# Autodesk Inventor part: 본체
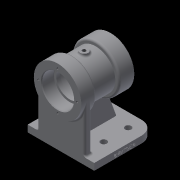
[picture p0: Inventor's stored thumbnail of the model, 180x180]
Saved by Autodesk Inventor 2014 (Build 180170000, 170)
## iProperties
Created: 2020-06
Part Number: 본체
Material: Generic
Document SubType Name: Modeling
Designer: kh
Density: 1 g/cm^3
Appearance: Default
Author: kh
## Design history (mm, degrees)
sketch "Sketch1"
  geometry: L1 (-45, -49)-(45, -49); L2 (45, -49)-(45, 49); L3 (45, 49)-(-45, 49); L4 (-45, 49)-(-45, -49); L5 (-45, -49)-(45, 49); L6 (45, -49)-(-45, 49); 1 further point
  constraints: 12 end point, 2 midpoint, 2 parallel, 1 horizontal, 1 perpendicular
  dimensions: "d0" = 90 distance of L2.end L3.end; "d1" = 98 distance of L1.end L2.end
extrude "Extrusion1" new body sketch "Sketch1" distance "d2" = 10; taper "d3" = 0 deg
fillet "Fillet1" dims "d4" = 20
workplane "Work Plane1"
sketch "Sketch2"
  geometry: L1 (-15.944, 80)-(113.944, 80); L2 (0, 0)-(98, 0) reference; C1 r 35 at (49, 80); 3 further points
  constraints: 2 end point, 2 midpoint, 1 centre point, 1 coincident, 1 horizontal, 1 vertical alignment
  dimensions: "d6" = 80 distance between parallel lines of L2 L1; "d7" = 70 diameter of C1
extrude "Extrusion2" join sketch "Sketch2" distance "d8" = 22; taper "d9" = 0 deg
sketch "Sketch3"
  geometry: C1 r 35 at (0, 0) reference; C2 r 29 at (0, 0); 1 further point
  constraints: 1 centre point, 1 coincident
  dimensions: "d10" = 58 diameter of C2
extrude "Extrusion3" join sketch "Sketch3" distance "d11" = 34; taper "d12" = 0 deg
sketch "Sketch4"
  geometry: C1 r 29 at (0, 0) reference; C2 r 35 at (0, 0); 1 further point
  constraints: 1 centre point, 1 coincident
  dimensions: "d13" = 70 diameter of C2
extrude "Extrusion4" join sketch "Sketch4" distance "d14" = 22; taper "d15" = 0 deg
workplane "Work Plane3"
sketch "Sketch5"
  geometry: L1 (50, 35)-(50, -35) reference; L2 (11, 35)-(11, -35); C1 r 6 at (11, 0); 2 further points
  constraints: 2 end point, 1 centre point, 1 coincident, 1 horizontal alignment, 1 midpoint, 1 parallel
  dimensions: "d18" = 39 distance between parallel lines of L2 L1; "d19" = 12 diameter of C1
extrude "Extrusion5" join sketch "Sketch5" distance "d20" = 22; taper "d21" = 0 deg
sketch "Sketch6"
  geometry: C1 r 35 at (0, 0) reference; C2 r 23.5 at (0, 0); 1 further point
  constraints: 1 centre point, 1 coincident
  dimensions: "d22" = 47 diameter of C2
extrude "Extrusion6" cut sketch "Sketch6" distance "d23" = 18; taper "d24" = 0 deg
sketch "Sketch7"
  geometry: C1 r 23.5 at (0, 0) reference; C2 r 20 at (0, 0); 1 further point
  constraints: 1 centre point, 1 coincident
  dimensions: "d25" = 40 diameter of C2
extrude "Extrusion7" cut sketch "Sketch7" distance "d26" = 6; taper "d27" = 0 deg
sketch "Sketch8"
  geometry: C1 r 20 at (0, 0) reference; C2 r 23 at (0, 0); 1 further point
  constraints: 1 centre point, 1 coincident
  dimensions: "d28" = 46 diameter of C2
extrude "Extrusion8" cut sketch "Sketch8" distance "d29" = 30; taper "d30" = 0 deg
sketch "Sketch9"
  geometry: C1 r 20 at (0, 0) reference; C2 r 20 at (0, 0); 1 further point
  constraints: 1 centre point, 1 coincident
  dimensions: "d31" = 40 diameter of C2
extrude "Extrusion9" cut sketch "Sketch9" distance "d32" = 6; taper "d33" = 0 deg
sketch "Sketch10"
  geometry: C1 r 35 at (0, 0) reference; C2 r 23.5 at (0, 0); 1 further point
  constraints: 1 centre point, 1 coincident
  dimensions: "d34" = 47 diameter of C2
extrude "Extrusion10" cut sketch "Sketch10" distance "d35" = 18; taper "d36" = 0 deg
sketch "Sketch12"
  geometry: L1 (-45, 0)-(-45, 10) reference; L2 (-45, 10)-(-45, 45); L3 (-50, 45)-(-28, 45) reference; L4 (20.261, 45)-(33, 10); L5 (6, 45)-(28, 45) reference; L6 (25, 10)-(45, 10) reference; L7 (-28, 45)-(-28, 115) reference; L8 (-28, 51)-(6, 51) reference; L9 (6, 115)-(6, 45) reference; L10 (25, 10)-(-45, 10) reference; L11 (-45, 45)-(-45, 48); L12 (-45, 48)-(-30, 48); L13 (-30, 48)-(-30, 53); L14 (-30, 53)-(8, 53); L15 (8, 53)-(8, 48); L16 (20.261, 45)-(19.169, 48); L17 (8, 48)-(19.169, 48); 1 further point
  constraints: 18 end point, 4 perpendicular, 3 point on line, 2 collinear, 2 parallel
  dimensions: "d40" = 70 deg angle of L4 L6; "d41" = 12 distance of L6.end L4.end; "d106" = 3 distance between parallel lines of L3 L12; "d107" = 2 distance between parallel lines of L7 L13; "d108" = 38 distance between parallel lines of L15 L13; "d109" = 2 distance between parallel lines of L8 L14; "d110" = 3 distance between parallel lines of L5 L17
sketch "Sketch13"
  geometry: L1 (0, 0)-(0, 10) reference; L2 (14, 10)-(84, 10); L3 (14, 10)-(14, 80); L4 (84, 10)-(84, 80); A1 r 35 centre (49, 80) between (49, 45) and (14, 80) reference; 2 further points
  constraints: 6 end point, 2 perpendicular, 2 point on circle, 1 midpoint, 1 tangent, 1 vertical alignment
  dimensions: "d45" = 70 distance of L2.start L2.end
extrude "Extrusion12" join sketch "Sketch13" distance "d46" = 10; taper "d47" = 0 deg
hole "Hole1" diameter "d50" = 5.188; stored, may be unused: countersink angle "d54" = 90 deg, drill point angle "d56" = 118 deg; dims "d51" = 6, "d52" = 4, "d53" = 2, "d55" = 22, "d121" = 10, "d122" = 10
sketch "Sketch14"
  geometry: C1 r 35 at (0, 0) reference; A1 r 28.5 centre (0, 0) between (0, 28.5) and (-28.5, 0); 3 further points
  constraints: 4 point on circle, 1 centre point, 1 coincident
  dimensions: "d57" = 57 diameter of A1
hole "Hole2" sketch "Sketch14" at (0, 28.5), (-28.5, 0), (28.5, 0), (0, -28.5) diameter "d58" = 3.242; stored, may be unused: countersink angle "d62" = 90 deg, drill point angle "d64" = 118 deg; dims "d59" = 10, "d60" = 4, "d61" = 2, "d63" = 12
sketch "Sketch15"
  geometry: C1 r 35 at (0, 0) reference; A1 r 28.5 centre (0, 0) between (0, 28.5) and (-28.5, 0); 3 further points
  constraints: 4 point on circle, 1 centre point, 1 coincident
  dimensions: "d65" = 57 diameter of A1
hole "Hole3" sketch "Sketch15" at (0, 28.5), (-28.5, 0), (0, -28.5), (28.5, 0) diameter "d66" = 3.242; stored, may be unused: countersink angle "d70" = 90 deg, drill point angle "d72" = 118 deg; dims "d67" = 10, "d68" = 4, "d69" = 2, "d71" = 12
sketch "Sketch16"
  geometry: L1 (45, -29)-(45, 29) reference; L2 (-45, 49)-(-45, 35) reference; L3 (-35, 35)-(-35, -35) reference; L4 (25, 42)-(25, -38.765); L5 (-11, 35)-(-11, -33.137); L6 (0, 0)-(45, 0); L7 (-21.226, 29)-(33.964, 29); L8 (25, -29)-(-21.226, -29); A1 r 20 centre (25, -29) between (25, -49) and (45, -29) reference; A2 r 20 centre (25, 29) between (45, 29) and (25, 49) reference; 5 further points
  constraints: 10 end point, 4 parallel, 4 point on line, 2 coincident, 1 midpoint
  dimensions: "d73" = 70 distance between parallel lines of L4 L2; "d74" = 36 distance between parallel lines of L4 L5; "d75" = 29 distance between parallel lines of L6 L7
hole "Hole4" sketch "Sketch16" at (-11, 29), (25, 29), (-11, -29), (25, -29) diameter "d76" = 9; stored, may be unused: countersink angle "d80" = 90 deg, drill point angle "d82" = 118 deg; dims "d77" = 10, "d78" = 4, "d79" = 2, "d81" = 12
fillet "Fillet2" dims "d83" = 3
fillet "Fillet4" dims "d85" = 3
fillet "Fillet6" dims "d87" = 3
fillet "Fillet7" dims "d88" = 3
fillet "Fillet10" dims "d91" = 3
chamfer "Chamfer1" distance "d94" = 1; stored, may be unused: second distance "d95" = 2, angle "d96" = 45 deg
fillet "Fillet13" dims "d97" = 0.3
fillet "Fillet14" dims "d102" = 3
fillet "Fillet15" dims "d103" = 3
extrude "Extrusion16" join sketch "Sketch12" stored distance "d111" = 10; taper "d112" = 0 deg
fillet "Fillet16" dims "d113" = 3
fillet "Fillet17" dims "d114" = 3
fillet "Fillet18" dims "d115" = 3
fillet "Fillet19" dims "d116" = 3
sketch "Sketch20"
  geometry: L1 (0, 0)-(0, 10) reference; 2 further points
  constraints: 1 other
  dimensions: "d117" = 45 distance from line of point (45, 4) L1; "d118" = 4 vertical distance of L1.start point (45, 4)
emboss "Emboss1" sketch "Sketch20" dims "d119" = 0.5, "d120" = 0
workplane "Work Plane4"
sketch "Sketch21"
  geometry: C1 r 20 at (0, 0) reference; C2 r 23 at (0, 0); 1 further point
  constraints: 1 centre point, 1 coincident
  dimensions: "d124" = 46 diameter of C2
extrude "Extrusion17" cut sketch "Sketch21" stored distance "d125" = 30; taper "d126" = 0 deg
body "Solid1"
other parameters: "d5" = 5, "d17" = 112, "d123" = -39
